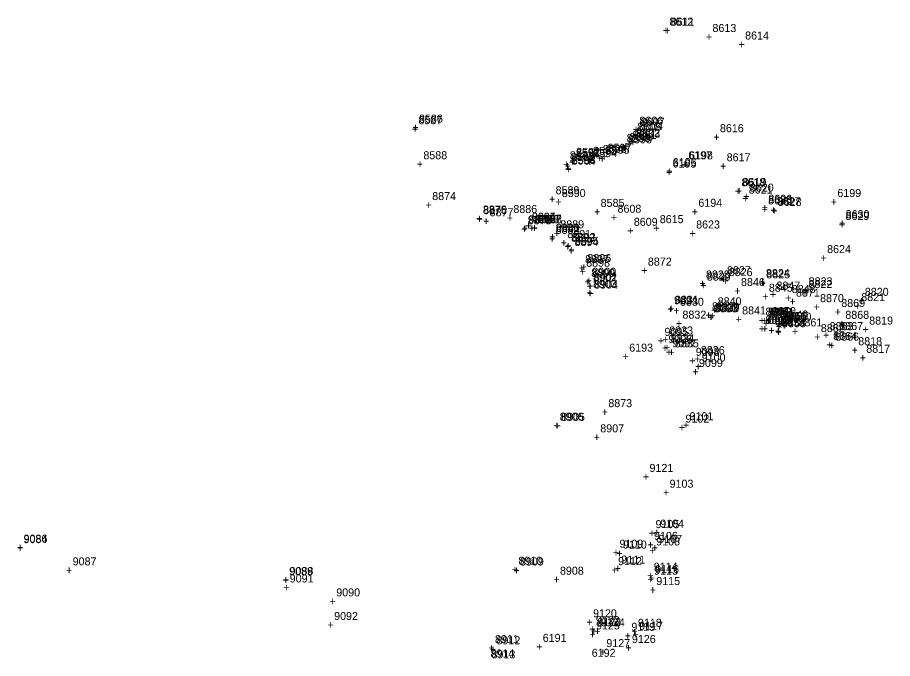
# Model space of a CAD drawing. Extents: x 1136220 to 1137808, y 528804 to 531215.
# Drawn here: x 1136219.9 to 1136493.2, y 529519.6 to 529719.8 of the extents above; entities that cross this region are included whole.
import ezdxf

# ---------------------------------------------------------------- set-up
doc = ezdxf.new("R2010")
doc.units = 0
for name, color, linetype in [('S_Buildings', 7, 'Continuous'), ('S_Buildings_SillElevation', 7, 'Continuous'), ('S_Buildings_Steps_Brick', 7, 'Continuous'), ('S_Curb_Type_3', 7, 'Continuous'), ('S_Drainage_CB', 7, 'Continuous'), ('S_Drainage_Culvert_Top', 7, 'Continuous'), ('S_Drainage_Invert', 7, 'Continuous'), ('S_Drainage_Sump', 7, 'Continuous'), ('S_Ground_Elevation', 7, 'Continuous'), ('S_Property_Garden', 7, 'Continuous'), ('S_Property_IronPipeFound', 7, 'Continuous'), ('S_Property_Walkways', 7, 'Continuous'), ('S_Roadway_Centerline', 7, 'Continuous'), ('S_Roadway_Drive_Paved', 7, 'Continuous'), ('S_Roadway_Edge_Pavement', 7, 'Continuous'), ('S_Traffic_Sign_SinglePost', 7, 'Continuous'), ('S_Trees_Bush', 7, 'Continuous'), ('S_Utilities_Gas_Gate', 7, 'Continuous'), ('S_Utilities_UG_Electrical_Line', 7, 'Continuous'), ('S_Utilities_UG_Gas_Line', 7, 'Continuous'), ('S_Utilities_UG_Sanitary_MH', 7, 'Continuous'), ('S_Utilities_UG_Water_Gate', 7, 'Continuous')]:
    doc.layers.add(name, color=color, linetype=linetype)

msp = doc.modelspace()

# ---------------------------------------------------------------- texts
at = {"layer": 'S_Buildings'}
for s, p in [('9093', (1136437.38, 529627.74)), ('8838', (1136437.8, 529627.8)), ('+', (1136435.32, 529624.99)), ('+', (1136435.74, 529625.05)), ('8866', (1136475.31, 529618.88)), ('+', (1136473.25, 529616.13)), ('9107', (1136420.04, 529555.74)), ('+', (1136417.98, 529552.99)), ('9116', (1136419.06, 529546.28)), ('+', (1136416.99, 529543.53)), ('9117', (1136414.04, 529528.59)), ('+', (1136411.98, 529525.84))]:
    msp.add_text(s, height=2.5, dxfattribs=at).set_placement(p)
at = {"layer": 'S_Buildings_SillElevation'}
for s, p in [('8857', (1136456.48, 529623.6)), ('+', (1136454.42, 529620.85)), ('9100', (1136433.59, 529612.34)), ('+', (1136431.52, 529609.59)), ('9101', (1136429.8, 529594.05)), ('+', (1136427.74, 529591.3)), ('9115', (1136419.4, 529542.56)), ('+', (1136417.34, 529539.81))]:
    msp.add_text(s, height=2.5, dxfattribs=at).set_placement(p)
at = {"layer": 'S_Buildings_Steps_Brick'}
for s, p in [('8851', (1136455.03, 529626.65)), ('8853', (1136454.4, 529624.12)), ('8852', (1136454.74, 529625.75)), ('8855', (1136458.77, 529624.83)), ('8856', (1136458.91, 529625.36)), ('+', (1136452.34, 529621.37)), ('+', (1136452.68, 529623)), ('+', (1136452.97, 529623.9)), ('+', (1136456.71, 529622.08)), ('+', (1136456.84, 529622.61)), ('8854', (1136458.49, 529623.41)), ('+', (1136456.43, 529620.66))]:
    msp.add_text(s, height=2.5, dxfattribs=at).set_placement(p)
at = {"layer": 'S_Curb_Type_3'}
for s, p in [('8612', (1136423.51, 529717.26)), ('+', (1136421.45, 529714.51)), ('8586', (1136345.27, 529686.98)), ('+', (1136343.21, 529684.23)), ('8605', (1136413.51, 529684.43)), ('8606', (1136414.12, 529686.35)), ('8600', (1136410.98, 529681.22)), ('+', (1136411.45, 529681.68)), ('8601', (1136411.99, 529681.9)), ('+', (1136412.06, 529683.6)), ('8602', (1136413.13, 529682.62)), ('+', (1136409.93, 529679.15)), ('8599', (1136410.14, 529680.89)), ('+', (1136411.07, 529679.87)), ('8592', (1136394.38, 529676.59)), ('8593', (1136399.64, 529676.91)), ('8596', (1136402.7, 529677.47)), ('8597', (1136404.19, 529677.86)), ('+', (1136408.08, 529678.14)), ('+', (1136408.92, 529678.47)), ('+', (1136392.32, 529673.84)), ('+', (1136397.58, 529674.16)), ('+', (1136400.64, 529674.72)), ('+', (1136402.13, 529675.11)), ('8619', (1136446.36, 529667.18)), ('8620', (1136448.63, 529665.42)), ('+', (1136444.3, 529664.43)), ('+', (1136446.57, 529662.67)), ('8626', (1136454.4, 529661.94)), ('8627', (1136457.09, 529661.18)), ('8876', (1136365.32, 529658.38)), ('8877', (1136367.33, 529657.73)), ('+', (1136452.34, 529659.19)), ('+', (1136455.03, 529658.43)), ('8630', (1136478.55, 529657.13)), ('+', (1136363.26, 529655.63)), ('+', (1136365.27, 529654.98)), ('8878', (1136379.23, 529655.21)), ('+', (1136476.49, 529654.38)), ('+', (1136377.17, 529652.46)), ('8882', (1136387.96, 529652.24)), ('+', (1136385.89, 529649.49)), ('8893', (1136392.81, 529649.78)), ('8894', (1136393.89, 529648.44)), ('+', (1136390.75, 529647.03)), ('+', (1136391.83, 529645.69)), ('8897', (1136397.17, 529643.1)), ('8898', (1136397.51, 529641.97)), ('+', (1136395.11, 529640.35)), ('+', (1136395.45, 529639.22)), ('8899', (1136399.09, 529638.81)), ('8902', (1136399.66, 529637.4)), ('+', (1136397.03, 529636.06)), ('8903', (1136399.64, 529635.35)), ('+', (1136397.58, 529632.6)), ('+', (1136397.6, 529634.65)), ('8906', (1136389.25, 529593.9)), ('+', (1136387.19, 529591.15)), ('8910', (1136376.34, 529548.93)), ('+', (1136374.28, 529546.18)), ('9125', (1136400.57, 529528.71)), ('9123', (1136400.97, 529529.74)), ('+', (1136398.51, 529525.96)), ('+', (1136398.91, 529526.99)), ('8911', (1136369.01, 529524.43)), ('+', (1136366.95, 529521.68)), ('8914', (1136367.62, 529519.95))]:
    msp.add_text(s, height=2.5, dxfattribs=at).set_placement(p)
at = {"layer": 'S_Drainage_CB'}
for s, p in [('8581', (1136392.39, 529675.51)), ('+', (1136390.33, 529672.76))]:
    msp.add_text(s, height=2.5, dxfattribs=at).set_placement(p)
at = {"layer": 'S_Drainage_Culvert_Top'}
for s, p in [('8584', (1136392.99, 529673.88)), ('+', (1136390.93, 529671.13)), ('8585', (1136402.02, 529660.66)), ('8886', (1136374.75, 529658.74)), ('+', (1136399.95, 529657.91)), ('+', (1136372.69, 529655.99)), ('8885', (1136380.55, 529656.35)), ('8888', (1136382.49, 529655.53)), ('8889', (1136389.42, 529653.96)), ('+', (1136378.49, 529653.6)), ('+', (1136380.42, 529652.78)), ('+', (1136387.36, 529651.21)), ('9086', (1136221.76, 529555.81)), ('+', (1136219.7, 529553.06)), ('9087', (1136237.09, 529548.7)), ('+', (1136235.03, 529545.95))]:
    msp.add_text(s, height=2.5, dxfattribs=at).set_placement(p)
at = {"layer": 'S_Drainage_Invert'}
for s, p in [('8583', (1136393.03, 529674.08)), ('+', (1136390.97, 529671.33)), ('8884', (1136380.54, 529656.3)), ('8887', (1136382.38, 529655.7)), ('+', (1136378.48, 529653.55)), ('+', (1136380.32, 529652.95)), ('9084', (1136221.75, 529555.65)), ('+', (1136219.69, 529552.9))]:
    msp.add_text(s, height=2.5, dxfattribs=at).set_placement(p)
at = {"layer": 'S_Drainage_Sump'}
for s, p in [('8582', (1136392.74, 529674.99)), ('+', (1136390.68, 529672.24)), ('8883', (1136381.61, 529655.58)), ('+', (1136379.55, 529652.83))]:
    msp.add_text(s, height=2.5, dxfattribs=at).set_placement(p)
at = {"layer": 'S_Ground_Elevation'}
for s, p in [('8829', (1136435.19, 529637.65)), ('8826', (1136442.04, 529639.05)), ('8825', (1136453.77, 529638.35)), ('+', (1136439.98, 529636.3)), ('8846', (1136445.86, 529635.93)), ('+', (1136451.71, 529635.6)), ('8822', (1136466.95, 529635.34)), ('+', (1136433.13, 529634.9)), ('+', (1136443.8, 529633.18)), ('8845', (1136454.56, 529634.16)), ('8871', (1136463.04, 529632.62)), ('+', (1136464.89, 529632.59)), ('8830', (1136426.81, 529629.78)), ('+', (1136452.5, 529631.41)), ('+', (1136460.97, 529629.87)), ('8870', (1136470.56, 529630.91)), ('8869', (1136477.19, 529629.38)), ('8821', (1136483.42, 529631.25)), ('+', (1136424.75, 529627.03)), ('8837', (1136436.79, 529628.37)), ('8844', (1136453.5, 529626.71)), ('+', (1136468.5, 529628.16)), ('+', (1136481.36, 529628.5)), ('+', (1136434.73, 529625.62)), ('+', (1136475.13, 529626.63)), ('8868', (1136478.45, 529625.7)), ('+', (1136451.43, 529623.97)), ('8861', (1136463.82, 529623.34)), ('8862', (1136470.8, 529621.57)), ('8863', (1136473.53, 529622.16)), ('+', (1136476.39, 529622.95)), ('8867', (1136476.56, 529622.19)), ('8833', (1136423.44, 529620.82)), ('8834', (1136423.85, 529618.32)), ('+', (1136461.76, 529620.59)), ('+', (1136468.74, 529618.82)), ('+', (1136471.47, 529619.41)), ('+', (1136474.5, 529619.44)), ('8864', (1136474.66, 529619.1)), ('+', (1136421.37, 529618.07)), ('8835', (1136425.23, 529616.8)), ('+', (1136472.6, 529616.35)), ('8818', (1136482.49, 529617.46)), ('+', (1136421.79, 529615.57)), ('+', (1136423.17, 529614.05)), ('8836', (1136433.33, 529614.69)), ('+', (1136480.43, 529614.71)), ('+', (1136431.27, 529611.94)), ('9110', (1136408.99, 529553.95)), ('9108', (1136419.37, 529554.94)), ('+', (1136406.93, 529551.2)), ('+', (1136417.31, 529552.19)), ('9111', (1136408.47, 529549.28)), ('+', (1136406.41, 529546.53)), ('9114', (1136418.6, 529547.05)), ('+', (1136416.54, 529544.3)), ('9124', (1136402.11, 529529.66)), ('+', (1136400.05, 529526.91)), ('9126', (1136411.79, 529524.48)), ('+', (1136409.73, 529521.73))]:
    msp.add_text(s, height=2.5, dxfattribs=at).set_placement(p)
at = {"layer": 'S_Property_Garden'}
for s, p in [('8840', (1136438.58, 529629.93)), ('+', (1136436.52, 529627.18)), ('8839', (1136437.98, 529628.22)), ('8841', (1136446.2, 529627.09)), ('8842', (1136454.25, 529626.65)), ('+', (1136435.91, 529625.47)), ('+', (1136444.14, 529624.34)), ('8843', (1136453.49, 529624.14)), ('8859', (1136459.41, 529625.3)), ('8860', (1136460.42, 529625.1)), ('+', (1136451.42, 529621.39)), ('+', (1136452.19, 529623.9)), ('+', (1136457.35, 529622.55)), ('+', (1136458.36, 529622.35)), ('8858', (1136458.67, 529623.09)), ('+', (1136456.61, 529620.34))]:
    msp.add_text(s, height=2.5, dxfattribs=at).set_placement(p)
at = {"layer": 'S_Property_IronPipeFound'}
for s, p in [('9091', (1136304.89, 529543.38)), ('+', (1136302.83, 529540.63))]:
    msp.add_text(s, height=2.5, dxfattribs=at).set_placement(p)
at = {"layer": 'S_Property_Walkways'}
for s, p in [('8847', (1136456.94, 529634.84)), ('8848', (1136461.72, 529633.74)), ('+', (1136454.88, 529632.09)), ('+', (1136459.66, 529630.99)), ('8850', (1136455.55, 529626.87)), ('+', (1136453.49, 529624.12)), ('8849', (1136459.47, 529625.8)), ('+', (1136457.41, 529623.05))]:
    msp.add_text(s, height=2.5, dxfattribs=at).set_placement(p)
at = {"layer": 'S_Roadway_Centerline'}
for s, p in [('8613', (1136436.95, 529715.27)), ('+', (1136434.89, 529712.52)), ('8588', (1136346.64, 529675.54)), ('+', (1136344.58, 529672.79)), ('8589', (1136387.95, 529664.61)), ('+', (1136385.89, 529661.86)), ('8608', (1136407.29, 529658.84)), ('+', (1136405.23, 529656.09)), ('8615', (1136420.49, 529655.58)), ('8623', (1136431.85, 529653.91)), ('+', (1136418.43, 529652.83)), ('+', (1136429.79, 529651.16)), ('8624', (1136472.76, 529646.23)), ('+', (1136470.7, 529643.48)), ('8872', (1136416.77, 529642.32)), ('+', (1136414.71, 529639.57)), ('8873', (1136404.42, 529598.12)), ('+', (1136402.36, 529595.37)), ('8907', (1136401.9, 529590.26)), ('+', (1136399.84, 529587.51)), ('8908', (1136389.31, 529545.79)), ('+', (1136387.25, 529543.04))]:
    msp.add_text(s, height=2.5, dxfattribs=at).set_placement(p)
at = {"layer": 'S_Roadway_Drive_Paved'}
for s, p in [('8820', (1136484.54, 529632.88)), ('+', (1136482.48, 529630.13)), ('8819', (1136485.91, 529623.91)), ('+', (1136483.85, 529621.16)), ('9096', (1136423.19, 529618.13)), ('9097', (1136424.43, 529616.83)), ('+', (1136421.13, 529615.38)), ('+', (1136422.37, 529614.08)), ('9098', (1136431.72, 529614.14)), ('8817', (1136484.99, 529615.08)), ('+', (1136429.66, 529611.39)), ('9099', (1136432.74, 529610.68)), ('+', (1136482.93, 529612.33)), ('+', (1136430.68, 529607.93)), ('9102', (1136428.52, 529593.29)), ('+', (1136426.46, 529590.54)), ('9103', (1136423.55, 529572.96)), ('+', (1136421.49, 529570.21)), ('9105', (1136419.16, 529560.33)), ('9104', (1136420.64, 529560.51)), ('+', (1136417.1, 529557.58)), ('+', (1136418.58, 529557.76)), ('9106', (1136418.69, 529556.67)), ('9109', (1136407.91, 529554.24)), ('+', (1136416.63, 529553.92)), ('+', (1136405.85, 529551.49)), ('9112', (1136407.46, 529548.78)), ('+', (1136405.4, 529546.03)), ('9113', (1136418.73, 529545.8)), ('+', (1136416.67, 529543.05)), ('9120', (1136399.64, 529532.49)), ('+', (1136397.58, 529529.74)), ('9119', (1136411.61, 529528.27)), ('9118', (1136413.67, 529529.52)), ('+', (1136411.61, 529526.77)), ('+', (1136409.55, 529525.52))]:
    msp.add_text(s, height=2.5, dxfattribs=at).set_placement(p)
at = {"layer": 'S_Roadway_Edge_Pavement'}
for s, p in [('8611', (1136423.92, 529717.23)), ('+', (1136421.86, 529714.48)), ('8614', (1136447.15, 529712.93)), ('+', (1136445.08, 529710.18)), ('8587', (1136345.11, 529686.49)), ('8604', (1136414.05, 529684.72)), ('8607', (1136414.53, 529686.01)), ('8616', (1136439.28, 529683.99)), ('+', (1136343.05, 529683.74)), ('+', (1136411.99, 529681.97)), ('+', (1136412.47, 529683.26)), ('8603', (1136413.18, 529682.27)), ('8598', (1136410.57, 529680.53)), ('+', (1136411.12, 529679.52)), ('+', (1136437.22, 529681.24)), ('8591', (1136394.26, 529676.19)), ('8594', (1136399.74, 529676.19)), ('8595', (1136403.58, 529677.26)), ('+', (1136408.51, 529677.78)), ('+', (1136392.19, 529673.44)), ('+', (1136397.68, 529673.44)), ('+', (1136401.52, 529674.51)), ('8617', (1136441.38, 529674.9)), ('+', (1136439.32, 529672.15)), ('8618', (1136446.02, 529667.09)), ('8621', (1136448.28, 529664.81)), ('8874', (1136349.4, 529662.78)), ('+', (1136443.96, 529664.34)), ('+', (1136347.34, 529660.03)), ('+', (1136446.22, 529662.06)), ('8625', (1136454.34, 529661.45)), ('8628', (1136457.34, 529660.97)), ('8875', (1136365.23, 529658.58)), ('+', (1136452.28, 529658.7)), ('+', (1136455.27, 529658.22)), ('8629', (1136478.52, 529656.58)), ('+', (1136363.17, 529655.83)), ('8879', (1136379.42, 529655.53)), ('+', (1136377.36, 529652.78)), ('8880', (1136387.98, 529652.88)), ('8881', (1136388.08, 529652.85)), ('+', (1136476.46, 529653.83)), ('+', (1136385.92, 529650.13)), ('+', (1136386.02, 529650.1)), ('8891', (1136391.61, 529650.95)), ('8892', (1136393, 529650.02)), ('8895', (1136393.98, 529648.8)), ('+', (1136389.55, 529648.2)), ('+', (1136390.94, 529647.27)), ('+', (1136391.92, 529646.05)), ('8896', (1136397.86, 529643.42)), ('+', (1136395.8, 529640.67)), ('8900', (1136399.43, 529639.16)), ('8901', (1136399.87, 529637.49)), ('8828', (1136434.91, 529638.29)), ('8827', (1136441.49, 529639.63)), ('8824', (1136453.66, 529638.74)), ('+', (1136397.37, 529636.41)), ('8904', (1136400.01, 529635.16)), ('+', (1136432.85, 529635.54)), ('+', (1136439.43, 529636.88)), ('+', (1136451.59, 529635.99)), ('8823', (1136467.01, 529636.17)), ('+', (1136397.81, 529634.74)), ('+', (1136397.95, 529632.41)), ('+', (1136464.95, 529633.42)), ('9094', (1136424.93, 529630.27)), ('8831', (1136425.18, 529630.42)), ('+', (1136422.87, 529627.52)), ('+', (1136423.12, 529627.67)), ('9095', (1136421.96, 529620.39)), ('+', (1136419.9, 529617.64)), ('8905', (1136389.67, 529593.84)), ('+', (1136387.61, 529591.1)), ('8909', (1136376.81, 529548.66)), ('+', (1136374.75, 529545.91)), ('9122', (1136400.53, 529530.32)), ('+', (1136398.46, 529527.57)), ('8912', (1136369.48, 529524.04)), ('+', (1136367.42, 529521.29)), ('8913', (1136367.92, 529519.66))]:
    msp.add_text(s, height=2.5, dxfattribs=at).set_placement(p)
at = {"layer": 'S_Traffic_Sign_SinglePost'}
for s, p in [('8832', (1136427.57, 529625.76)), ('+', (1136425.51, 529623.01))]:
    msp.add_text(s, height=2.5, dxfattribs=at).set_placement(p)
at = {"layer": 'S_Trees_Bush'}
for s, p in [('9127', (1136403.8, 529523.18)), ('+', (1136401.74, 529520.43))]:
    msp.add_text(s, height=2.5, dxfattribs=at).set_placement(p)
at = {"layer": 'S_Utilities_Gas_Gate'}
for s, p in [('6196', (1136424.54, 529673.38)), ('6197', (1136429.41, 529675.51)), ('+', (1136422.48, 529670.63)), ('+', (1136427.35, 529672.76))]:
    msp.add_text(s, height=2.5, dxfattribs=at).set_placement(p)
at = {"layer": 'S_Utilities_UG_Electrical_Line'}
for s, p in [('9089', (1136304.71, 529545.6)), ('9088', (1136304.83, 529545.72)), ('+', (1136302.65, 529542.85)), ('+', (1136302.77, 529542.97)), ('9090', (1136319.43, 529539.02)), ('+', (1136317.36, 529536.27))]:
    msp.add_text(s, height=2.5, dxfattribs=at).set_placement(p)
at = {"layer": 'S_Utilities_UG_Gas_Line'}
for s, p in [('6195', (1136424.49, 529672.95)), ('6198', (1136429.64, 529675.5)), ('+', (1136427.57, 529672.75)), ('+', (1136422.43, 529670.2)), ('6199', (1136475.96, 529663.74)), ('+', (1136473.9, 529660.99)), ('6193', (1136410.94, 529615.45)), ('+', (1136408.88, 529612.7)), ('6191', (1136383.92, 529524.82)), ('+', (1136381.86, 529522.07)), ('6192', (1136399.23, 529520.15))]:
    msp.add_text(s, height=2.5, dxfattribs=at).set_placement(p)
at = {"layer": 'S_Utilities_UG_Sanitary_MH'}
for s, p in [('6194', (1136432.54, 529660.68)), ('+', (1136430.48, 529657.93)), ('9092', (1136318.76, 529531.64)), ('+', (1136316.7, 529528.89))]:
    msp.add_text(s, height=2.5, dxfattribs=at).set_placement(p)
at = {"layer": 'S_Utilities_UG_Water_Gate'}
for s, p in [('8590', (1136389.89, 529663.73)), ('+', (1136387.82, 529660.98)), ('8609', (1136412.37, 529654.74)), ('+', (1136410.3, 529651.99)), ('9121', (1136417.28, 529577.89)), ('+', (1136415.21, 529575.14))]:
    msp.add_text(s, height=2.5, dxfattribs=at).set_placement(p)

doc.saveas('drawing.dxf')
